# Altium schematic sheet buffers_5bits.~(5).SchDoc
size A4
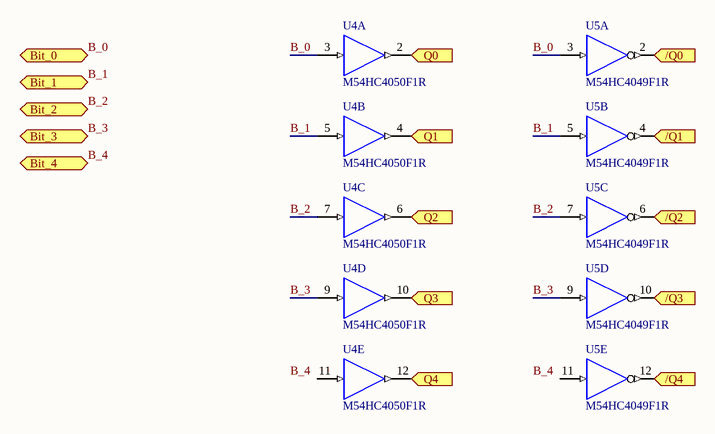
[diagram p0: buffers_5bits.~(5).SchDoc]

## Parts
U4  M54HC4050F1R  [DIP16]  (parts A,B,C,D,E of 6)
U5  M54HC4049F1R  [DIP16]  (parts A,B,C,D,E of 6)

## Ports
/Q0 (out), /Q1 (out), /Q2 (out), /Q3 (out), /Q4 (out), Bit_0 (in), Bit_1 (in), Bit_2 (in), Bit_3 (in), Bit_4 (in), Q0 (out), Q1 (out), Q2 (out), Q3 (out), Q4 (out)

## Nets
GND: U4.8(GND) U5.8(GND)
VCC: U4.1(VCC) U5.1(VCC)
/Q0: U5.2(Y) ; port /Q0
/Q1: U5.4(Y) ; port /Q1
/Q2: U5.6(Y) ; port /Q2
/Q3: U5.10(Y) ; port /Q3
/Q4: U5.12(Y) ; port /Q4
B_0: U4.3(A) U5.3(A) ; port Bit_0
B_1: U4.5(A) U5.5(A) ; port Bit_1
B_2: U4.7(A) U5.7(A) ; port Bit_2
B_3: U4.9(A) U5.9(A) ; port Bit_3
Q0: U4.2(Y) ; port Q0
Q1: U4.4(Y) ; port Q1
Q2: U4.6(Y) ; port Q2
Q3: U4.10(Y) ; port Q3
Q4: U4.12(Y) ; port Q4

Not connected (* = marked no-connect by the designer): U4 11(A); U5 11(A)

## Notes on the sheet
- Labels drawn without touching a wire or pin: B_4

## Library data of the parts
U4 = M54HC4050F1R: Hex Buffer/Converter Non-Inverting; Note: Pins 13 and 16 are not connected and not drawn.
U5 = M54HC4049F1R: Hex Buffer/Converter Invertering; Note: Pins 13 and 16 are not connected and not drawn.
